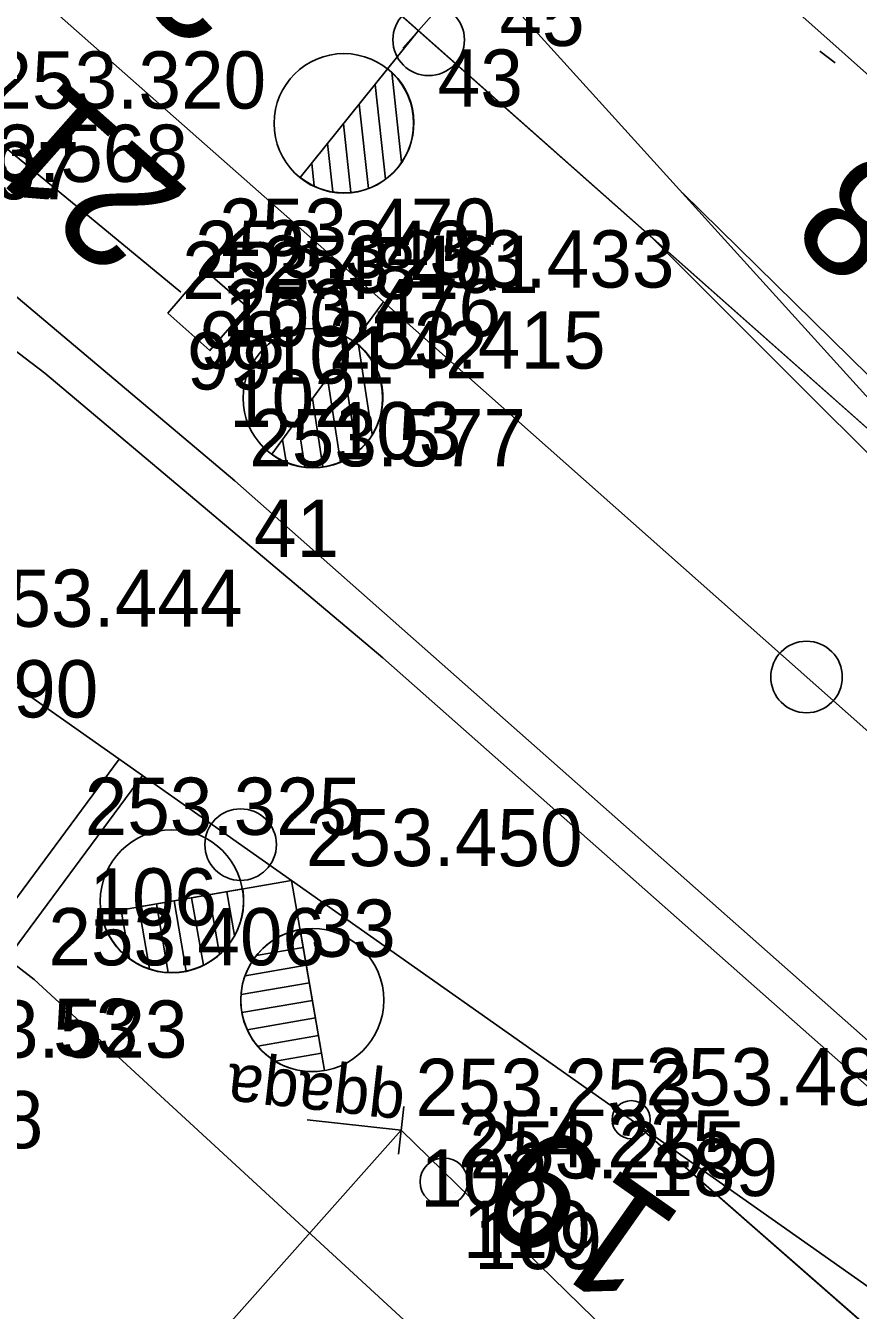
# Model space of a CAD drawing. Extents: x -496688 to -495455, y -1089309 to -1088026.
# Drawn here: x -495985.25 to -495967.8, y -1088634.51 to -1088607.59 of the extents above; entities that cross this region are included whole.
import ezdxf

# ---------------------------------------------------------------- set-up
doc = ezdxf.new("R2010")
doc.units = 0
for name, color, linetype in [('Vrstva 1', 7, 'Continuous'), ('Vrstva 12', 7, 'Continuous'), ('Vrstva 13', 7, 'Continuous'), ('Vrstva 2', 7, 'Continuous'), ('Vrstva 36', 7, 'Continuous'), ('Vrstva 49', 7, 'Continuous'), ('Vrstva 6', 7, 'Continuous'), ('Vrstva 60', 7, 'Continuous'), ('Vrstva 61', 7, 'Continuous'), ('Vrstva 63', 7, 'Continuous'), ('Vrstva 7', 7, 'Continuous')]:
    doc.layers.add(name, color=color, linetype=linetype)

msp = doc.modelspace()

# ---------------------------------------------------------------- linework, layer by layer
at = {"layer": 'Vrstva 1'}
msp.add_line((-495958.584, -1088642.764), (-495972.56, -1088630.52), dxfattribs=at)
for points in [[(-495794.281, -1088769.662), (-495806.718, -1088758.644), (-495819.114, -1088747.662), (-495828.107, -1088739.648), (-495840.608, -1088728.579), (-495852.984, -1088717.621), (-495860.029, -1088711.42), (-495872.461, -1088700.397), (-495884.955, -1088689.319), (-495893.533, -1088681.721), (-495913.179, -1088664.263), (-495947.105, -1088634.191), (-495952.116, -1088629.76), (-495964.613, -1088618.686), (-495984.901, -1088600.717), (-495997.336, -1088589.715), (-496002.819, -1088584.884), (-496021.751, -1088568.167), (-496024.418, -1088565.811), (-496062.504, -1088532.205), (-496086.773, -1088510.767), (-496106.199, -1088493.629), (-496127.249, -1088474.987), (-496164.633, -1088441.927)], [(-495916.136, -1088667.962), (-495923.285, -1088661.656), (-495935.688, -1088650.668), (-495948.162, -1088639.613), (-495977.755, -1088613.379), (-495990.206, -1088602.384), (-496002.656, -1088591.386), (-496007.627, -1088586.973), (-496020.065, -1088575.979), (-496027.948, -1088569.009), (-496033.091, -1088564.46), (-496045.526, -1088553.442), (-496057.996, -1088542.394), (-496059.439, -1088541.128), (-496090.012, -1088514.139), (-496109.155, -1088497.226), (-496130.335, -1088478.506), (-496167.718, -1088445.393)], [(-495875.462, -1088716.542), (-495884.273, -1088707.491), (-495892.725, -1088698.131), (-495899.76, -1088690.34), (-495906.824, -1088682.54), (-495918.092, -1088670.104), (-495924.53, -1088662.996), (-495935.688, -1088650.668), (-495946.859, -1088638.317), (-495948.839, -1088636.121), (-495953.409, -1088631.059), (-495964.613, -1088618.686), (-495975.723, -1088606.415), (-495978.55, -1088603.323), (-495987.022, -1088593.978), (-495995.49, -1088584.636), (-496004.032, -1088575.362), (-496012.801, -1088565.84)], [(-495903.705, -1088678.98), (-495917.323, -1088669.371), (-495925.246, -1088663.805), (-495938.946, -1088654.176), (-495952.525, -1088644.634), (-495954.862, -1088642.985), (-495958.022, -1088640.767), (-495972.56, -1088630.52), (-495979.681, -1088625.505), (-495986.807, -1088620.489), (-496002.959, -1088609.142), (-496027.436, -1088591.913), (-496060.399, -1088568.783)], [(-495980.867, -1088617.126), (-495987.952, -1088611.164), (-495998.702, -1088602.96), (-496004.397, -1088598.979), (-496012.079, -1088593.993)], [(-496006.199, -1088611.844), (-495997.355, -1088618.062), (-495985.077, -1088627.584), (-495972.743, -1088638.936), (-495962.754, -1088650.285), (-495961.996, -1088651.249), (-495953.81, -1088663.645), (-495949.093, -1088672.316), (-495942.044, -1088686.532), (-495939.964, -1088690.857)], [(-495906.824, -1088682.54), (-495919.267, -1088671.496), (-495926.418, -1088665.233), (-495938.946, -1088654.176), (-495951.359, -1088643.225), (-495953.413, -1088641.405), (-495980.867, -1088617.126)]]:
    msp.add_lwpolyline(points, dxfattribs=at)
at = {"layer": 'Vrstva 12'}
msp.add_lwpolyline([(-495982.272, -1088613.615), (-495981.496, -1088612.714), (-495980.6, -1088613.49), (-495981.39, -1088614.4), (-495982.272, -1088613.615)], dxfattribs=at)
at = {"layer": 'Vrstva 13'}
msp.add_lwpolyline([(-495981.329, -1088594.451), (-495976.662, -1088600.548), (-495964.664, -1088611.227), (-495963.319, -1088612.424)], dxfattribs=at)
at = {"layer": 'Vrstva 2'}
for p, q in [((-495977.348, -1088608.063), (-495976.684, -1088607.315)), ((-495977.662, -1088608.489), (-495977.016, -1088607.689)), ((-495977.663, -1088608.489), (-495979.496, -1088610.771)), ((-495979.496, -1088610.771), (-495977.662, -1088608.49)), ((-495977.662, -1088608.49), (-495977.663, -1088608.489)), ((-495977.58, -1088608.566), (-495977.374, -1088610.453)), ((-495977.929, -1088608.82), (-495977.714, -1088610.807)), ((-495978.262, -1088609.233), (-495978.069, -1088610.999)), ((-495978.593, -1088609.648), (-495978.438, -1088611.083)), ((-495978.926, -1088610.061), (-495978.816, -1088611.07)), ((-495979.258, -1088610.475), (-495979.207, -1088610.949)), ((-495978.365, -1088614.207), (-495977.755, -1088613.379)), ((-495978.365, -1088614.208), (-495980.093, -1088616.57)), ((-495980.093, -1088616.57), (-495978.365, -1088614.209)), ((-495978.365, -1088614.209), (-495978.365, -1088614.208)), ((-495978.278, -1088614.281), (-495977.987, -1088616.157)), ((-495978.616, -1088614.55), (-495978.31, -1088616.526)), ((-495978.929, -1088614.978), (-495978.657, -1088616.734)), ((-495979.242, -1088615.407), (-495979.021, -1088616.834)), ((-495979.555, -1088615.835), (-495979.399, -1088616.839)), ((-495979.868, -1088616.264), (-495979.795, -1088616.734)), ((-495979.681, -1088625.505), (-495983.667, -1088626.198)), ((-495978.988, -1088629.491), (-495979.681, -1088625.505)), ((-495983.667, -1088626.198), (-495980.704, -1088625.683)), ((-495981.774, -1088625.868), (-495981.528, -1088627.282)), ((-495981.404, -1088625.805), (-495981.187, -1088627.052)), ((-495981.035, -1088625.741), (-495980.875, -1088626.66)), ((-495983.251, -1088626.126), (-495983.075, -1088627.143)), ((-495982.882, -1088626.061), (-495982.658, -1088627.357)), ((-495982.512, -1088625.997), (-495982.264, -1088627.431)), ((-495982.143, -1088625.933), (-495981.888, -1088627.405)), ((-495979.497, -1088626.541), (-495979.608, -1088626.559)), ((-495978.988, -1088629.491), (-495979.498, -1088626.533)), ((-495979.434, -1088626.91), (-495980.419, -1088627.081)), ((-495979.37, -1088627.28), (-495980.652, -1088627.501)), ((-495979.305, -1088627.649), (-495980.736, -1088627.897)), ((-495979.242, -1088628.019), (-495980.719, -1088628.275)), ((-495979.178, -1088628.388), (-495980.607, -1088628.636)), ((-495979.115, -1088628.758), (-495980.388, -1088628.979)), ((-495979.051, -1088629.127), (-495980.018, -1088629.295))]:
    msp.add_line(p, q, dxfattribs=at)
for points in [[(-495977.016, -1088607.689), (-495984.901, -1088600.717), (-495997.336, -1088589.715)], [(-495977.755, -1088613.379), (-495990.206, -1088602.384), (-496002.656, -1088591.386)], [(-495953.409, -1088631.059), (-495964.613, -1088618.686), (-495975.723, -1088606.415)], [(-495952.116, -1088629.76), (-495964.613, -1088618.686), (-495977.016, -1088607.689)], [(-495979.681, -1088625.505), (-495986.807, -1088620.489), (-496001.271, -1088610.315)], [(-495955.858, -1088626.444), (-495971.486, -1088611.095)], [(-495956.492, -1088627.654), (-495972.099, -1088612.056)], [(-495979.681, -1088625.505), (-495972.56, -1088630.52), (-495958.022, -1088640.767)], [(-495972.56, -1088630.52), (-495958.584, -1088642.764)]]:
    msp.add_lwpolyline(points, dxfattribs=at)
for centre, radius in [((-495978.583, -1088609.637), 1.462), ((-495979.232, -1088615.396), 1.462), ((-495982.189, -1088625.941), 1.5), ((-495979.245, -1088628.013), 1.5), ((-495972.56, -1088630.52), 0.4)]:
    msp.add_circle(centre, radius, dxfattribs=at)
for centre, radius, start, end in [((-495978.58, -1088609.63), 1.464, 231.2228, 51.1837), ((-495979.229, -1088615.389), 1.464, 233.8259, 53.7867), ((-495982.187, -1088625.932), 1.504, 190.1771, 9.5125), ((-495979.243, -1088628.012), 1.501, 99.7874, 279.7672)]:
    msp.add_arc(centre, radius, start, end, dxfattribs=at)
at = {"layer": 'Vrstva 36'}
for points in [[(-495982.001, -1088613.178), (-495986.312, -1088609.628), (-495992.007, -1088605.254), (-495994.985, -1088602.919), (-496012.279, -1088590.201), (-496017.631, -1088586.544), (-496026.239, -1088581.024), (-496029.453, -1088578.634), (-496040.554, -1088570.808), (-496043.73, -1088568.341), (-496063.489, -1088552.926), (-496089.159, -1088531.511), (-496093.567, -1088527.59), (-496121.596, -1088502.694)], [(-495977.383, -1088630.742), (-495971.326, -1088636.646)]]:
    msp.add_lwpolyline(points, dxfattribs=at)
at = {"layer": 'Vrstva 49'}
msp.add_lwpolyline([(-495935.845, -1088657.888), (-495950.312, -1088645.117), (-495977.766, -1088620.838), (-495984.851, -1088614.876), (-495995.601, -1088606.672), (-496001.296, -1088602.691), (-496013.309, -1088594.893)], dxfattribs=at)
at = {"layer": 'Vrstva 6'}
for p, q in [((-495977.438, -1088631.239), (-495977.328, -1088630.245)), ((-495995.595, -1088651.227), (-495977.383, -1088630.742)), ((-495979.351, -1088630.525), (-495977.383, -1088630.742))]:
    msp.add_line(p, q, dxfattribs=at)
at = {"layer": 'Vrstva 60'}
for p, q in [((-495977.016, -1088607.689), (-495977.016, -1088607.689)), ((-495977.016, -1088607.689), (-495977.016, -1088607.689)), ((-495981.496, -1088612.714), (-495981.496, -1088612.714)), ((-495981.496, -1088612.714), (-495981.496, -1088612.714)), ((-495982.001, -1088613.178), (-495982.001, -1088613.178)), ((-495982.001, -1088613.178), (-495982.001, -1088613.178)), ((-495980.6, -1088613.49), (-495980.6, -1088613.49)), ((-495980.6, -1088613.49), (-495980.6, -1088613.49)), ((-495977.755, -1088613.379), (-495977.755, -1088613.379)), ((-495977.755, -1088613.379), (-495977.755, -1088613.379)), ((-495982.272, -1088613.615), (-495982.272, -1088613.615)), ((-495982.272, -1088613.615), (-495982.272, -1088613.615)), ((-495981.39, -1088614.4), (-495981.39, -1088614.4)), ((-495981.39, -1088614.4), (-495981.39, -1088614.4)), ((-495979.199, -1088615.078), (-495979.199, -1088615.078)), ((-495979.199, -1088615.078), (-495979.199, -1088615.078)), ((-495980.867, -1088617.126), (-495980.867, -1088617.126)), ((-495980.867, -1088617.126), (-495980.867, -1088617.126)), ((-495984.316, -1088624.85), (-495984.316, -1088624.85)), ((-495984.316, -1088624.85), (-495984.316, -1088624.85)), ((-495979.681, -1088625.505), (-495979.681, -1088625.505)), ((-495979.681, -1088625.505), (-495979.681, -1088625.505)), ((-495985.077, -1088627.584), (-495985.077, -1088627.584)), ((-495985.077, -1088627.584), (-495985.077, -1088627.584)), ((-495977.383, -1088630.742), (-495977.383, -1088630.742)), ((-495977.383, -1088630.742), (-495977.383, -1088630.742)), ((-495972.56, -1088630.52), (-495972.56, -1088630.52)), ((-495972.56, -1088630.52), (-495972.56, -1088630.52)), ((-495976.487, -1088631.82), (-495976.487, -1088631.82)), ((-495976.487, -1088631.82), (-495976.487, -1088631.82)), ((-495976.253, -1088632.051), (-495976.253, -1088632.051)), ((-495976.253, -1088632.051), (-495976.253, -1088632.051))]:
    msp.add_line(p, q, dxfattribs=at)
at = {"layer": 'Vrstva 63'}
msp.add_line((-495968.289, -1088608.371), (-495968.605, -1088608.124), dxfattribs=at)
at = {"layer": 'Vrstva 7'}
for p, q in [((-495986.095, -1088626.752), (-495983.293, -1088622.962)), ((-495985.63, -1088627.132), (-495982.803, -1088623.307)), ((-495976.451, -1088631.854), (-495976.523, -1088631.786))]:
    msp.add_line(p, q, dxfattribs=at)
for centre, radius in [((-495976.806, -1088607.887), 0.75), ((-495968.886, -1088621.241), 0.75), ((-495980.747, -1088624.754), 0.75), ((-495976.487, -1088631.82), 0.5)]:
    msp.add_circle(centre, radius, dxfattribs=at)

# ---------------------------------------------------------------- texts
at = {"layer": 'Vrstva 2'}
for s, rotation, p in [('22', 138.4688, (-495979.952, -1088606.355)), ('21', 138.4984, (-495981.759, -1088611.11)), ('18', 138.4618, (-495964.88, -1088612.547)), ('19', 144.8583, (-495971.407, -1088632.578))]:
    msp.add_text(s, height=2.5, rotation=rotation, dxfattribs=at).set_placement(p)
at = {"layer": 'Vrstva 6'}
msp.add_text('qqaqa', height=1, rotation=173.7237, dxfattribs=at).set_placement((-495977.274, -1088629.748))
at = {"layer": 'Vrstva 60'}
for s, p in [('45', (-495975.323, -1088608.015)), ('45', (-495975.323, -1088608.015)), ('43', (-495976.616, -1088609.289)), ('43', (-495976.616, -1088609.289)), ('97', (-495985.912, -1088611.228)), ('97', (-495985.912, -1088611.228)), ('100', (-495981.096, -1088614.314)), ('100', (-495981.096, -1088614.314)), ('98', (-495981.601, -1088614.778)), ('98', (-495981.601, -1088614.778)), ('42', (-495977.355, -1088614.979)), ('42', (-495977.355, -1088614.979)), ('99', (-495981.872, -1088615.215)), ('99', (-495981.872, -1088615.215)), ('101', (-495980.2, -1088615.09)), ('101', (-495980.2, -1088615.09)), ('102', (-495980.99, -1088616)), ('102', (-495980.99, -1088616)), ('103', (-495978.799, -1088616.678)), ('103', (-495978.799, -1088616.678)), ('41', (-495980.467, -1088618.726)), ('41', (-495980.467, -1088618.726)), ('190', (-495986.407, -1088622.089)), ('190', (-495986.407, -1088622.089)), ('106', (-495983.916, -1088626.45)), ('106', (-495983.916, -1088626.45)), ('33', (-495979.281, -1088627.105)), ('33', (-495979.281, -1088627.105)), ('53', (-495984.677, -1088629.184)), ('53', (-495984.677, -1088629.184)), ('148', (-495987.561, -1088631.12)), ('148', (-495987.561, -1088631.12)), ('189', (-495972.16, -1088632.12)), ('189', (-495972.16, -1088632.12)), ('108', (-495976.983, -1088632.342)), ('108', (-495976.983, -1088632.342)), ('110', (-495976.087, -1088633.42)), ('110', (-495976.087, -1088633.42)), ('109', (-495975.853, -1088633.651)), ('109', (-495975.853, -1088633.651))]:
    msp.add_text(s, height=1.2, dxfattribs=at).set_placement(p)
at = {"layer": 'Vrstva 61'}
for s, p in [('253.320', (-495986.012, -1088609.328)), ('253.320', (-495986.012, -1088609.328)), ('253.568', (-495987.652, -1088610.864)), ('253.568', (-495987.652, -1088610.864)), ('253.470', (-495981.196, -1088612.414)), ('253.470', (-495981.196, -1088612.414)), ('253.343', (-495981.701, -1088612.878)), ('253.343', (-495981.701, -1088612.878)), ('253.433', (-495977.455, -1088613.079)), ('253.433', (-495977.455, -1088613.079)), ('253.481', (-495981.972, -1088613.315)), ('253.481', (-495981.972, -1088613.315)), ('253.461', (-495980.3, -1088613.19)), ('253.461', (-495980.3, -1088613.19)), ('253.476', (-495981.09, -1088614.1)), ('253.476', (-495981.09, -1088614.1)), ('253.415', (-495978.899, -1088614.778)), ('253.415', (-495978.899, -1088614.778)), ('253.577', (-495980.567, -1088616.826)), ('253.577', (-495980.567, -1088616.826)), ('253.444', (-495986.507, -1088620.189)), ('253.444', (-495986.507, -1088620.189)), ('253.325', (-495984.016, -1088624.55)), ('253.325', (-495984.016, -1088624.55)), ('253.450', (-495979.381, -1088625.205)), ('253.450', (-495979.381, -1088625.205)), ('253.406', (-495984.777, -1088627.284)), ('253.406', (-495984.777, -1088627.284)), ('253.523', (-495987.661, -1088629.22)), ('253.523', (-495987.661, -1088629.22)), ('253.483', (-495972.26, -1088630.22)), ('253.483', (-495972.26, -1088630.22)), ('253.253', (-495977.083, -1088630.442)), ('253.253', (-495977.083, -1088630.442)), ('254.225', (-495976.187, -1088631.52)), ('254.225', (-495976.187, -1088631.52)), ('253.255', (-495975.953, -1088631.751)), ('253.255', (-495975.953, -1088631.751))]:
    msp.add_text(s, height=1.2, dxfattribs=at).set_placement(p)

doc.saveas('drawing.dxf')
